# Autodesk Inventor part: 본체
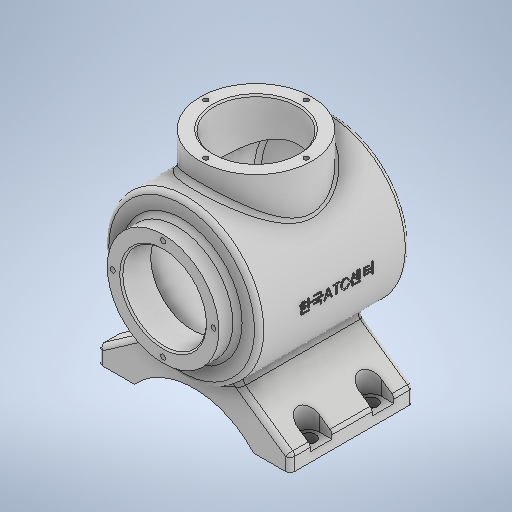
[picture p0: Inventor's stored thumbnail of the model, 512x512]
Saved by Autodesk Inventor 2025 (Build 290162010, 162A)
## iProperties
Created: 2024-07
Part Number: 본체
Material: 일반
Document SubType Name: Modeling
Designer: 계정
Density: 1 g/cm^3
Appearance: 기본값
Author: 계정
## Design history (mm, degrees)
sketch "스케치2"
  geometry: L1 (-0.621, -24.022)-(-62, -67); L2 (-62, -67)-(-62, -77); L3 (-62, -77)-(62, -77); L4 (62, -77)-(62, -67); L5 (62, -67)-(0.621, -24.022); L6 (0.621, -24.022)-(-0.621, -24.022); L7 (0, 38.547)-(0, -47.746); A1 r 52.096 centre (0, -112.096) between (38.5, -77) and (-38.5, -77); 3 further points
  constraints: 14 end point, 4 perpendicular, 3 point on circle, 3 point on line, 1 centre point, 1 midpoint, 1 vertical, 1 vertical alignment, 2 other
  dimensions: "d3" = 10 distance of L1.end L2.end; "d4" = 55 deg angle of L5 L4; "d5" = 77 distance from line of point (0, 0) L3; "d6" = 124 distance of L2.end L3.end; "d7" = 17 distance from line of L3 point (0, -60); "d8" = 77 distance of A1.start A1.end; "d104" = 10 distance of L3.end L4.end (derived)
extrude "돌출2" join sketch "스케치2" stored distance "d9" = 80; taper "d10" = 0 deg
sketch "스케치3"
  geometry: L1 (50, -48.336)-(-50, -48.336); L2 (-50, -48.336)-(-50, 48); L3 (-50, 48)-(50, 48); L4 (50, 48)-(50, -48.336); L5 (-0.621, 40)-(0.621, 40) reference; L6 (0.621, -40)-(0.621, 40) reference; L7 (-0.621, 40)-(0.621, 40) reference; L8 (-0.621, -40)-(-0.621, 40) reference; L9 (0.621, -40)-(-0.621, -40) reference; L10 (62, -40)-(62, 40) reference; L11 (-62, -40)-(-62, 40) reference; L12 (-67.633, 0)-(66.391, 0); L13 (0, -60)-(0, 119.018); A1 r 113 centre (0, 53) between (-50, -48.336) and (50, -48.336); 6 further points
  constraints: 12 end point, 3 midpoint, 3 point on circle, 2 horizontal, 2 parallel, 1 centre point, 1 perpendicular, 1 vertical
  dimensions: "d13" = 100 distance of L2.end L3.end; "d15" = 226 diameter of A1; "d16" = 108 distance from line of L3 L13.start; "d18" = 48 distance from line of point (-0.621, 0) L3; "d19" = 62 distance from line of L10 point (0, 48)
revolve "회전1" sketch "스케치3" stored, may be unused: angle "d20" = 90 deg
sketch "스케치4"
  geometry: C1 r 36 at (0, 0); 1 further point
  constraints: 1 centre point, 1 coincident
  dimensions: "d21" = 72 diameter of C1
extrude "돌출3" join sketch "스케치4" distance "d22" = 12; taper "d23" = 0 deg
sketch "스케치6"
  geometry: C1 r 36 at (0, 0); 1 further point
  constraints: 1 centre point, 1 coincident
  dimensions: "d34" = 72 diameter of C1
extrude "돌출4" join sketch "스케치6" distance "d35" = 65; taper "d36" = 0 deg
sketch "스케치5"
  geometry: L1 (0, 73.578)-(0, -117.524); L2 (36, 60)-(-36, 60) reference; L3 (0, 60)-(27, 60); L4 (27, 60)-(27, 41); L5 (27, 41)-(43, 41); L6 (43, 41)-(43, -43.887); A1 r 113 centre (0, 53) between (-50, -48.336) and (50, -48.336) reference; A2 r 106 centre (0, 53) between (0, -53) and (43, -43.887); 3 further points
  constraints: 10 end point, 3 perpendicular, 3 point on line, 2 point on circle, 1 centre point, 1 collinear, 1 horizontal, 1 midpoint, 1 vertical
  dimensions: "d24" = 19 distance of L3.end L4.end; "d25" = 86 diameter of L5.end L1; "d26" = 54 diameter of L3.end L1; "d27" = 7 radial gap between concentric circles of A1 A2
revolve "회전2" sketch "스케치5" stored, may be unused: angle "d28" = 360 deg
fillet "모깎기1" dims "d29" = 3
fillet "모깎기2" dims "d30" = 3
chamfer "모따기1" distance "d31" = 1; stored, may be unused: second distance "d32" = 2, angle "d33" = 45 deg
sketch "스케치7"
  geometry: C1 r 36 at (0, 0) reference; 2 further points
  constraints: 1 coincident
hole "구멍1" sketch "스케치7" at (0, 0) diameter "d37" = 54; stored, may be unused: countersink angle "d41" = 90 deg, drill point angle "d43" = 0 deg; dims "d38" = 8, "d39" = 4, "d40" = 2, "d42" = 45
chamfer "모따기2" distance "d44" = 1; stored, may be unused: second distance "d45" = 2, angle "d46" = 45 deg
fillet "모깎기3" dims "d47" = 3
fillet "모깎기4" dims "d48" = 3
fillet "모깎기5" dims "d49" = 3
fillet "모깎기6" dims "d50" = 3
fillet "모깎기7" dims "d51" = 3
node "작업 평면1"
sketch "스케치8"
  geometry: L1 (70, -20)-(54, -20); L2 (70, -13)-(54, -13); L3 (54, -27)-(70, -27); L4 (62, 37)-(62, -37) reference; L5 (38.5, -40)-(59, -40) reference; L6 (54, 13)-(70, 13); L7 (70, 27)-(54, 27); L8 (-70, -27)-(-54, -27); L9 (-54, -13)-(-70, -13); L10 (-70, 13)-(-54, 13); L11 (-54, 27)-(-70, 27); L12 (-62, -37)-(-62, 37) reference; L13 (-38.5, 40)-(-59, 40) reference; L14 (-59, -40)-(-38.5, -40) reference; L15 (59, 40)-(38.5, 40) reference; A1 r 7 centre (70, -20) between (70, -27) and (70, -13); A2 r 7 centre (54, -20) between (54, -13) and (54, -27); A3 r 7 centre (54, 20) between (54, 27) and (54, 13); A4 r 7 centre (70, 20) between (70, 13) and (70, 27); A5 r 7 centre (-70, -20) between (-70, -13) and (-70, -27); A6 r 7 centre (-54, -20) between (-54, -27) and (-54, -13); A7 r 7 centre (-70, 20) between (-70, 27) and (-70, 13); A8 r 7 centre (-54, 20) between (-54, 13) and (-54, 27); 8 further points
  constraints: 20 end point, 16 point on circle, 16 tangent, 8 centre point, 7 midpoint, 5 point on line, 4 parallel, 1 horizontal
  dimensions: "d53" = 8 distance from line of L4 L1.end; "d54" = 20 distance between parallel lines of L5 L1; "d55" = 14 distance of point (62, -13) point (62, -27); "d56" = 8 distance from line of L4 A3.centre; "d57" = 8 distance from line of L12 A6.centre; "d58" = 8 distance from line of L12 A8.centre; "d59" = 20 distance from line of A8.centre L13; "d60" = 20 distance from line of A6.centre L14; "d61" = 14 distance between parallel lines of L9 L8; "d62" = 14 distance between parallel lines of L11 L10; "d63" = 20 distance from line of A4.centre L15; "d64" = 14 distance between parallel lines of L6 L7; "d65" = 108 distance of A6.centre L1.end (derived); "d66" = 40 distance of A3.centre L1.end; "d67" = 40 distance of A7.centre A5.centre
extrude "돌출5" cut sketch "스케치8" distance "d68" = 20; taper "d69" = 0 deg
sketch "스케치9"
  geometry: A1 r 7 centre (-54, 20) between (-54, 13) and (-54, 27) reference; A2 r 7 centre (-54, -20) between (-54, -27) and (-54, -13) reference; A3 r 7 centre (54, -20) between (54, -13) and (54, -27) reference; A4 r 7 centre (54, 20) between (54, 27) and (54, 13) reference; 5 further points
  constraints: 4 coincident
hole "구멍2" sketch "스케치9" at (-54, 20), (-54, -20), (54, 20), (54, -20) diameter "d70" = 9; stored, may be unused: countersink angle "d74" = 90 deg, drill point angle "d76" = 0 deg; dims "d71" = 6, "d72" = 4, "d73" = 2, "d75" = 45
fillet "모깎기8" dims "d77" = 3
sketch "스케치10"
  geometry: 2 further points
  constraints: 1 horizontal alignment
  dimensions: "d85" = 32.5 distance of point (-32.5, 0) point (0, 0)
hole "구멍3" sketch "스케치10" at (-32.5, 0) diameter "d78" = 3.242; stored, may be unused: countersink angle "d82" = 90 deg, drill point angle "d84" = 120 deg; dims "d79" = 8, "d80" = 4, "d81" = 2, "d83" = 10
sketch "스케치11"
  geometry: 2 further points
  constraints: 1 vertical alignment
  dimensions: "d96" = 32.5 distance of point (0, 32.5) point (0, 0)
hole "구멍4" sketch "스케치11" at (0, 32.5) diameter "d89" = 3.242; stored, may be unused: countersink angle "d93" = 90 deg, drill point angle "d95" = 120 deg; dims "d90" = 8, "d91" = 4, "d92" = 2, "d94" = 10
node "작업 평면2"
sketch "스케치12"
  geometry: L1 (36, 60)-(-36, 60) reference; 3 further points
  constraints: 2 vertical alignment, 1 midpoint, 1 other
  dimensions: "d101" = 62 distance from line of L1 point (0, -2)
feature "엠보싱1" sketch "스케치12" dims "d3" = 10, "d4" = 55 deg, "d5" = 77, "d6" = 124, "d7" = 17, "d8" = 77, "d102" = 0.5, "d103" = 0, "d104" = 10 (derived)
node "솔리드1"
pattern_circular "원형 패턴1" dims angle "d87" = 360 deg
pattern_circular "원형 패턴2" dims angle "d98" = 360 deg
node "투영된 루프1"
feature "A9D066F2-1C7D-4E18-AEED-F7BC21143FA4" dims "d37" = 54, "d38" = 8, "d39" = 4, "d40" = 2, "d41" = 90 deg, "d42" = 45, "d43" = 0
other parameters: "d52" = -71, "d100" = 174
